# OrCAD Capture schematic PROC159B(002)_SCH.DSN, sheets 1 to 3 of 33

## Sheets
1 11. CURRENT MONITORING DEVICES: size C; title: CURRENT MONITORING DEVICES; rev: B
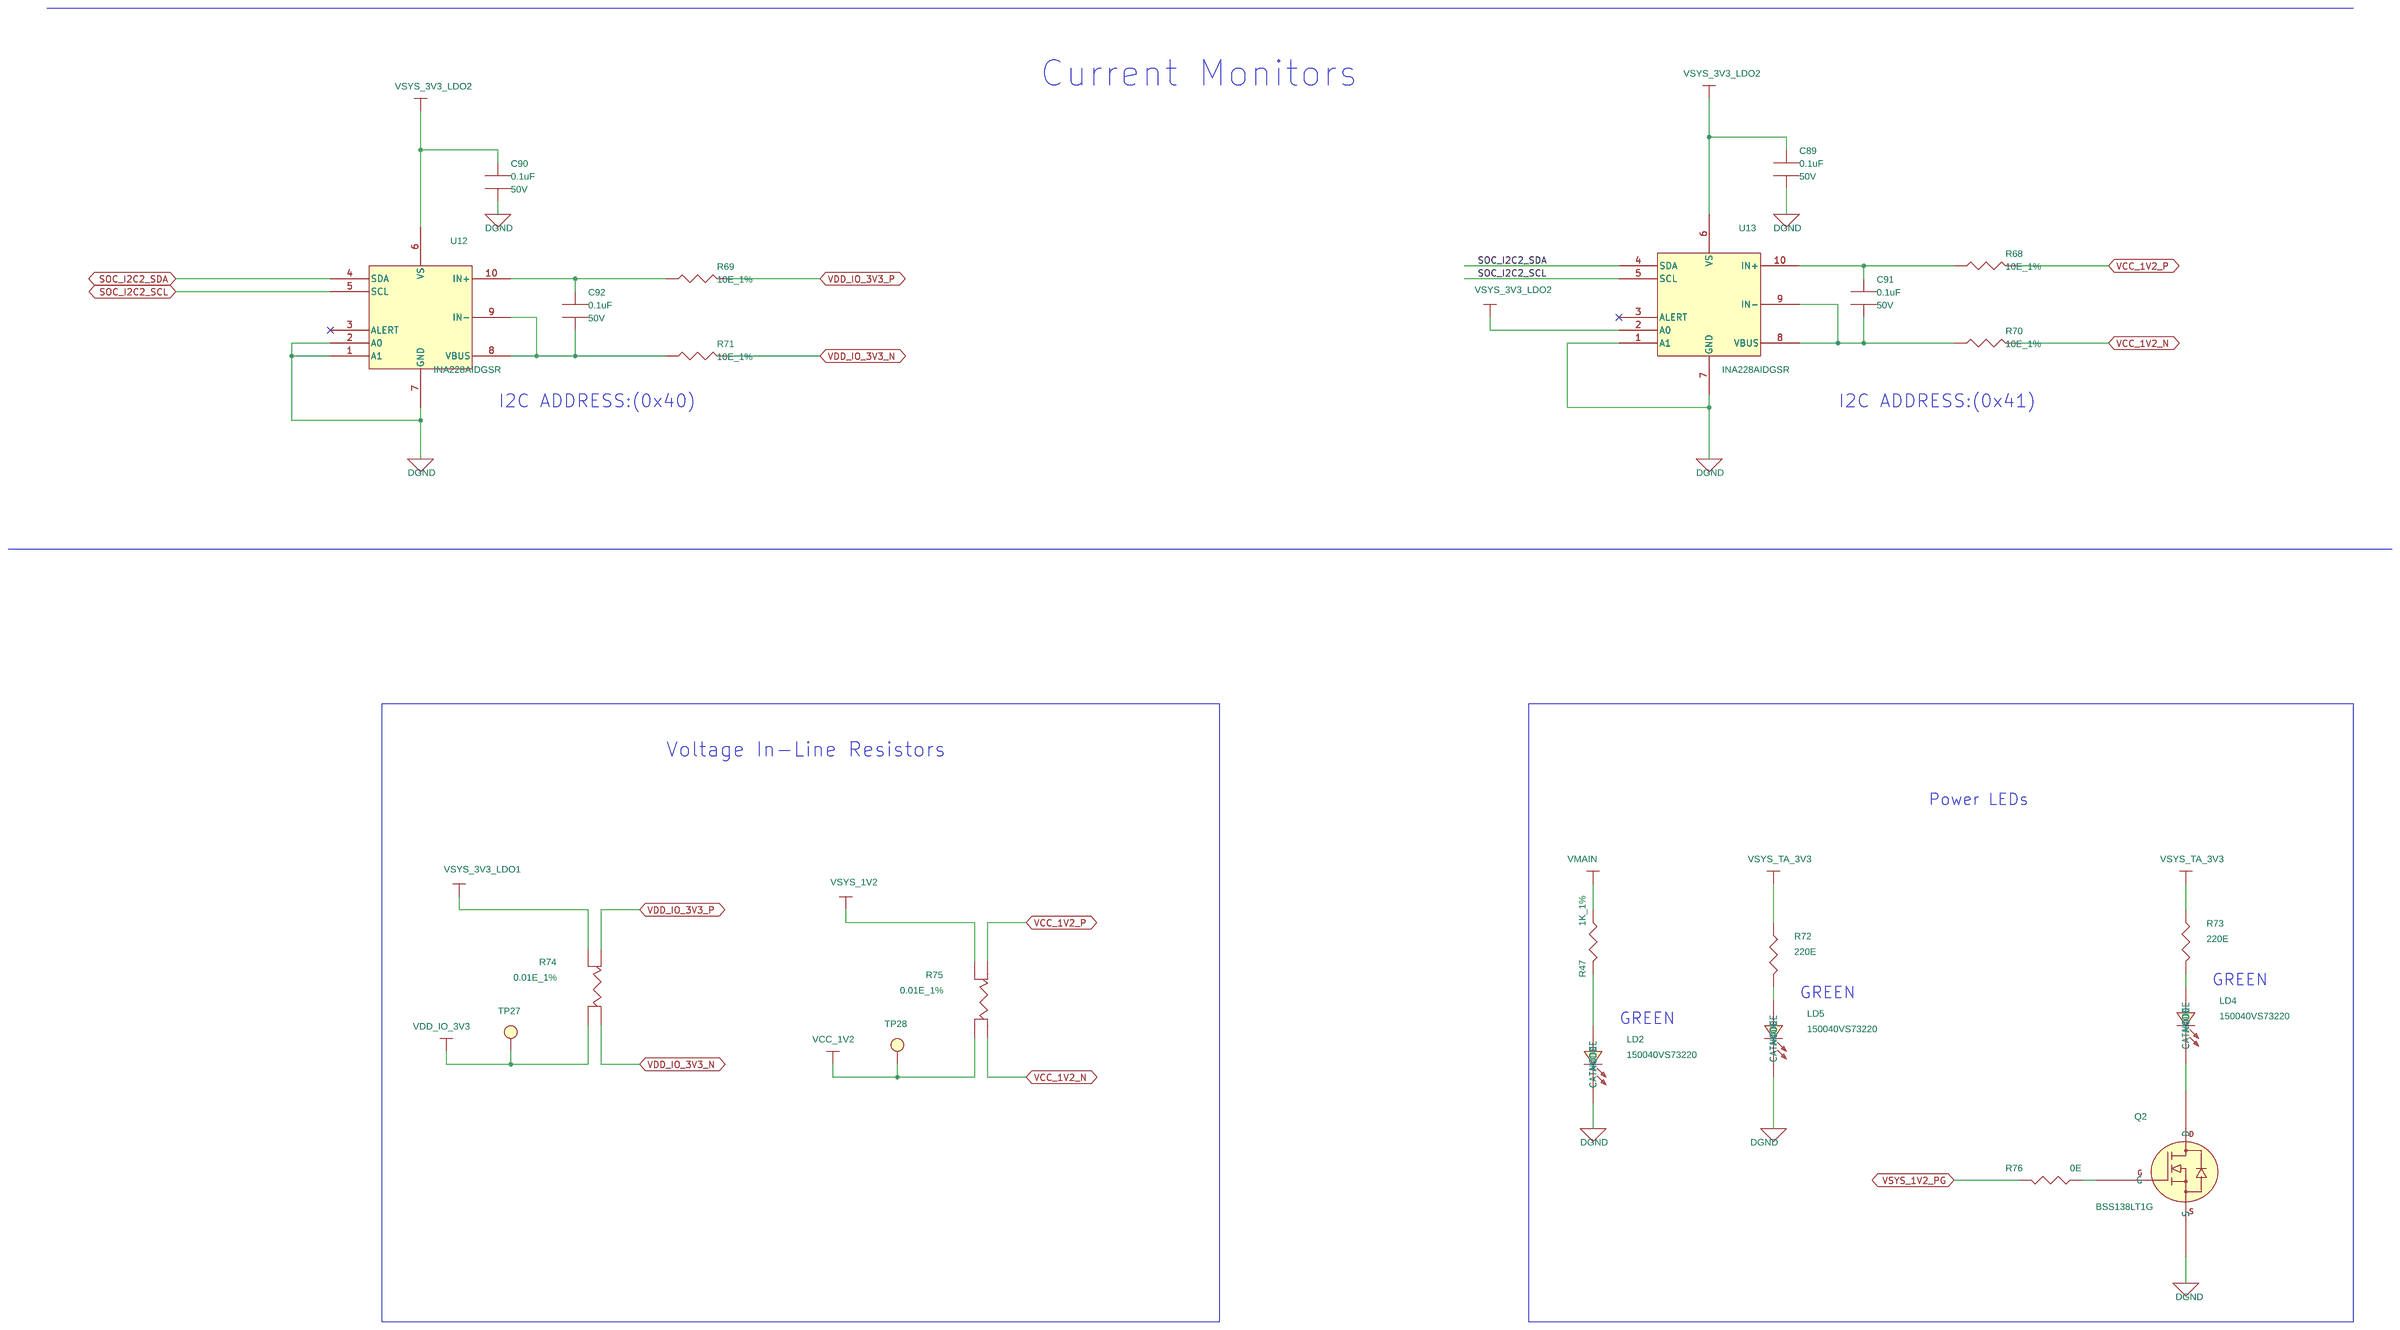
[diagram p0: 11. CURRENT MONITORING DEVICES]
2 30. ADC  MUXES: size C; title: ADC MUXES
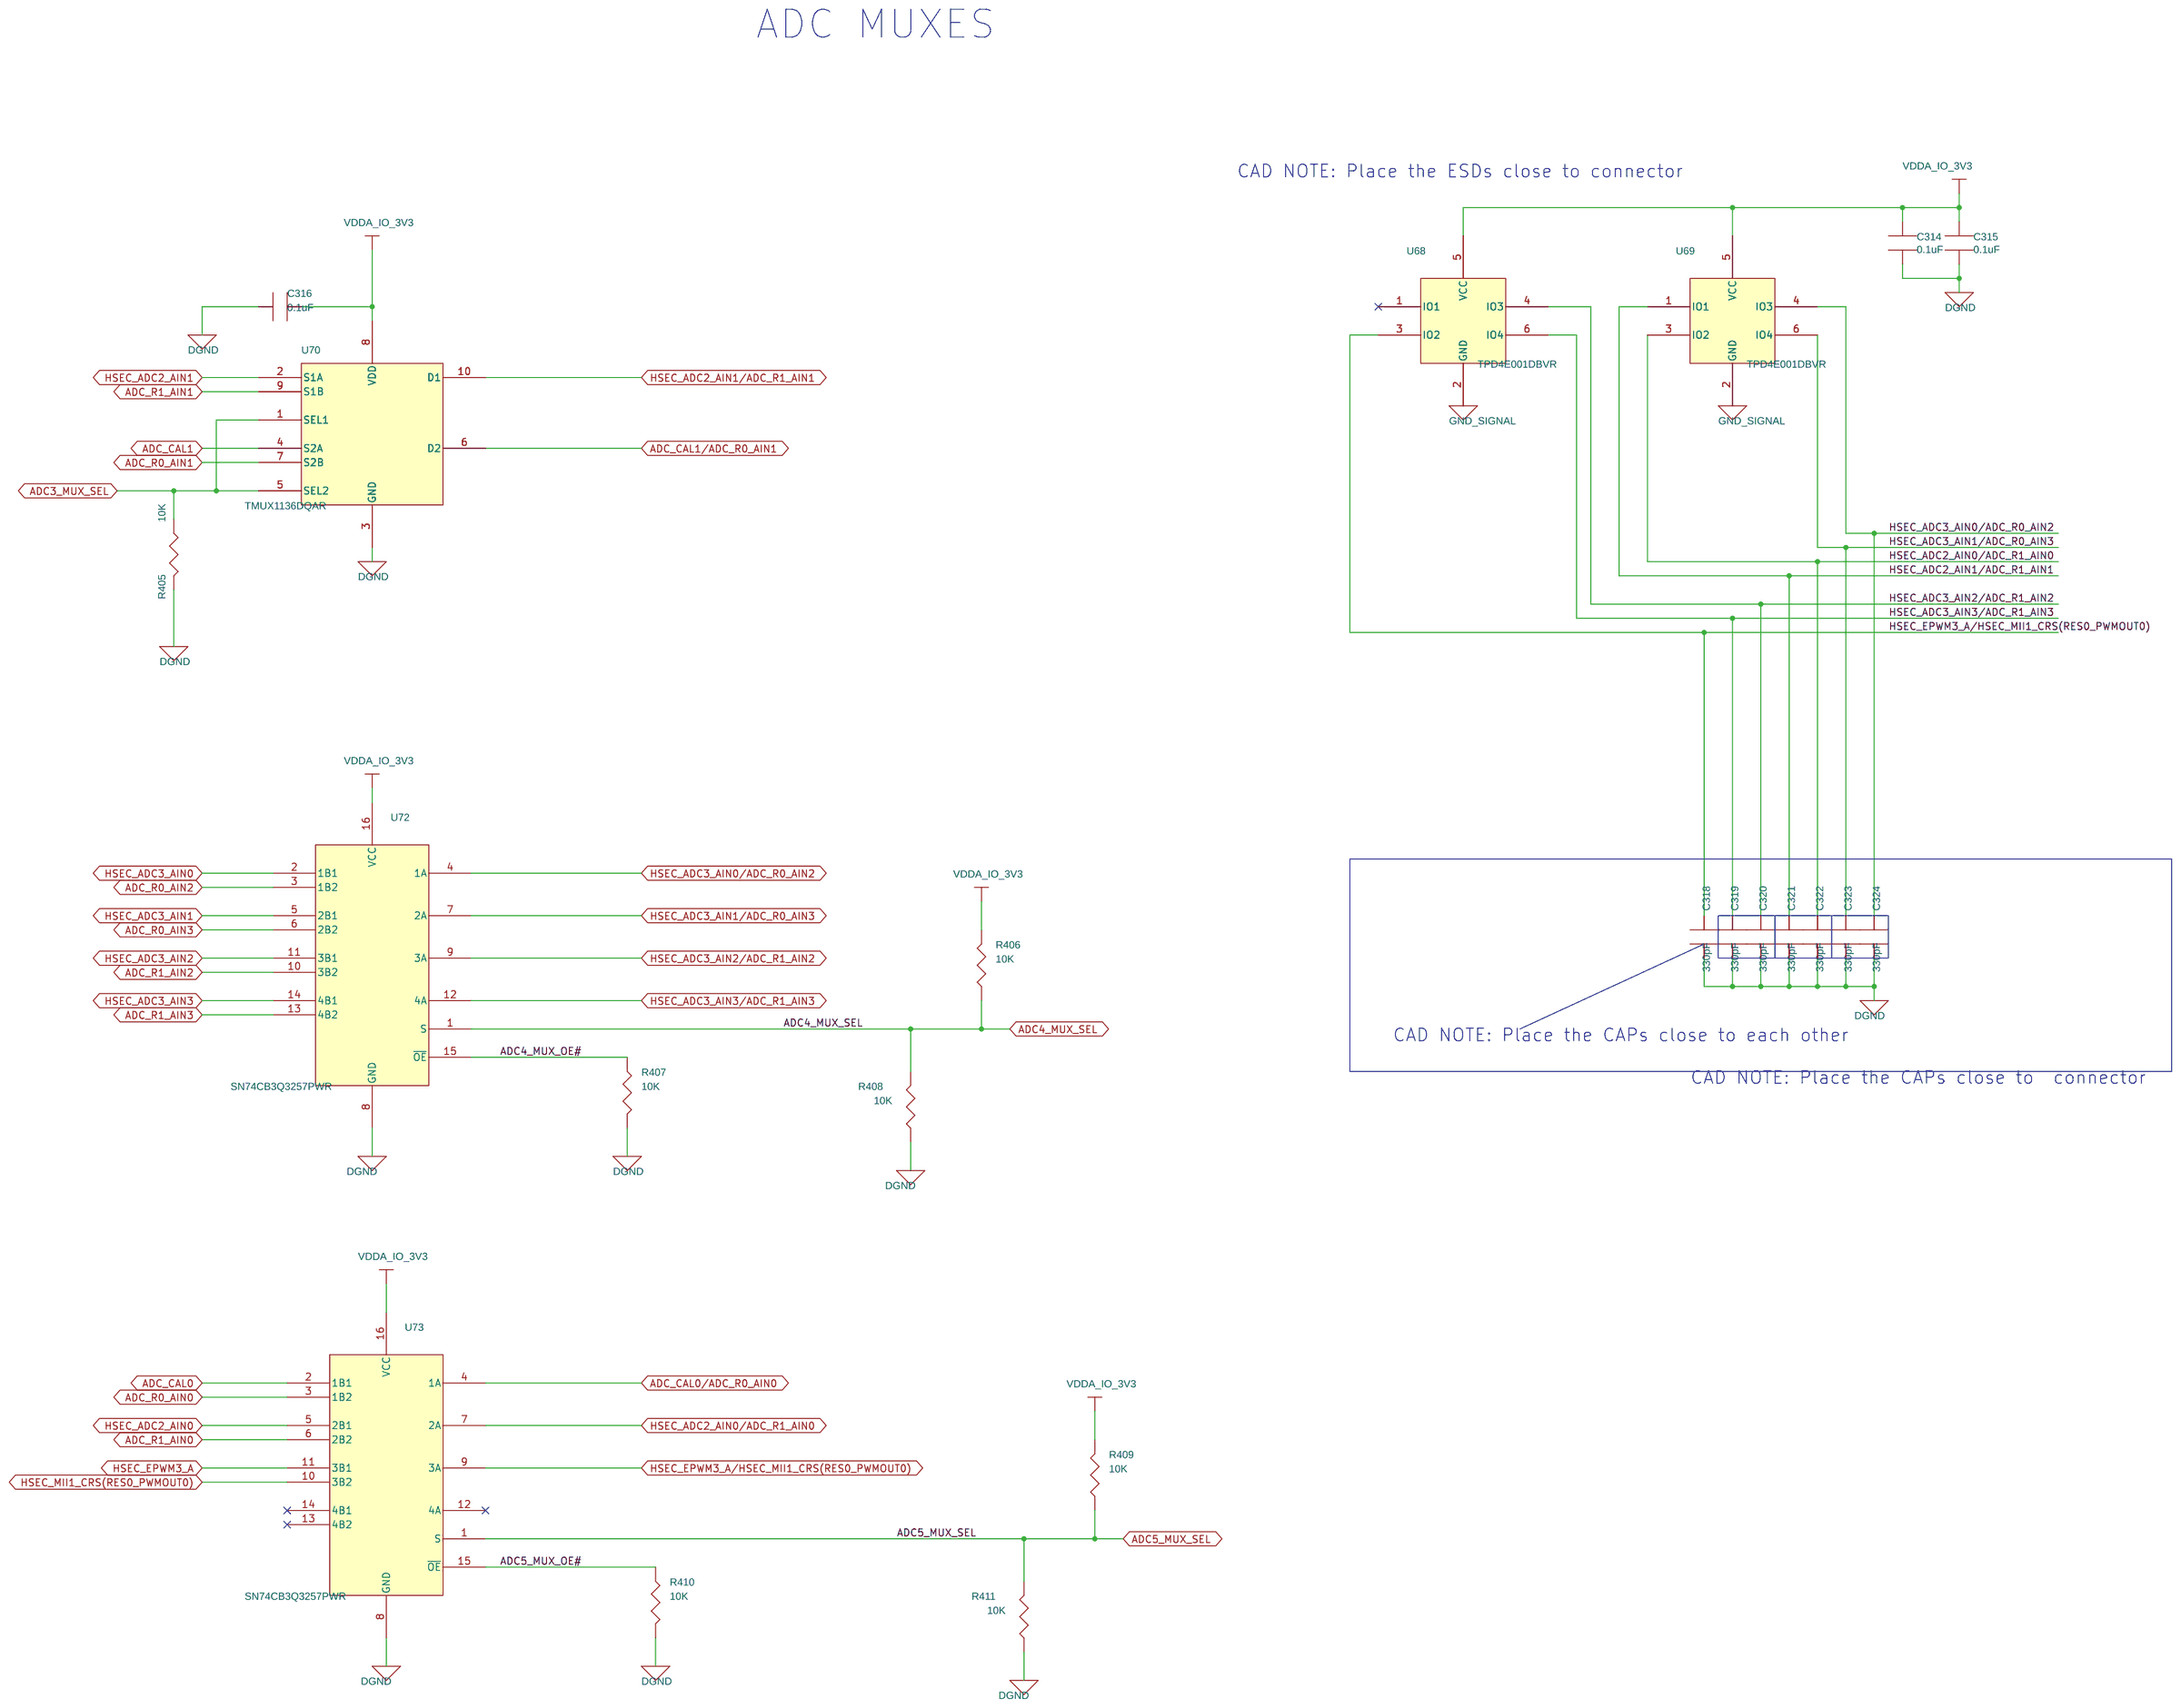
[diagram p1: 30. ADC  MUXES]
3 27. AUTOMATION SIGNALS BUFFER: size C; title: AUTOMATION SIGNALS BUFFER
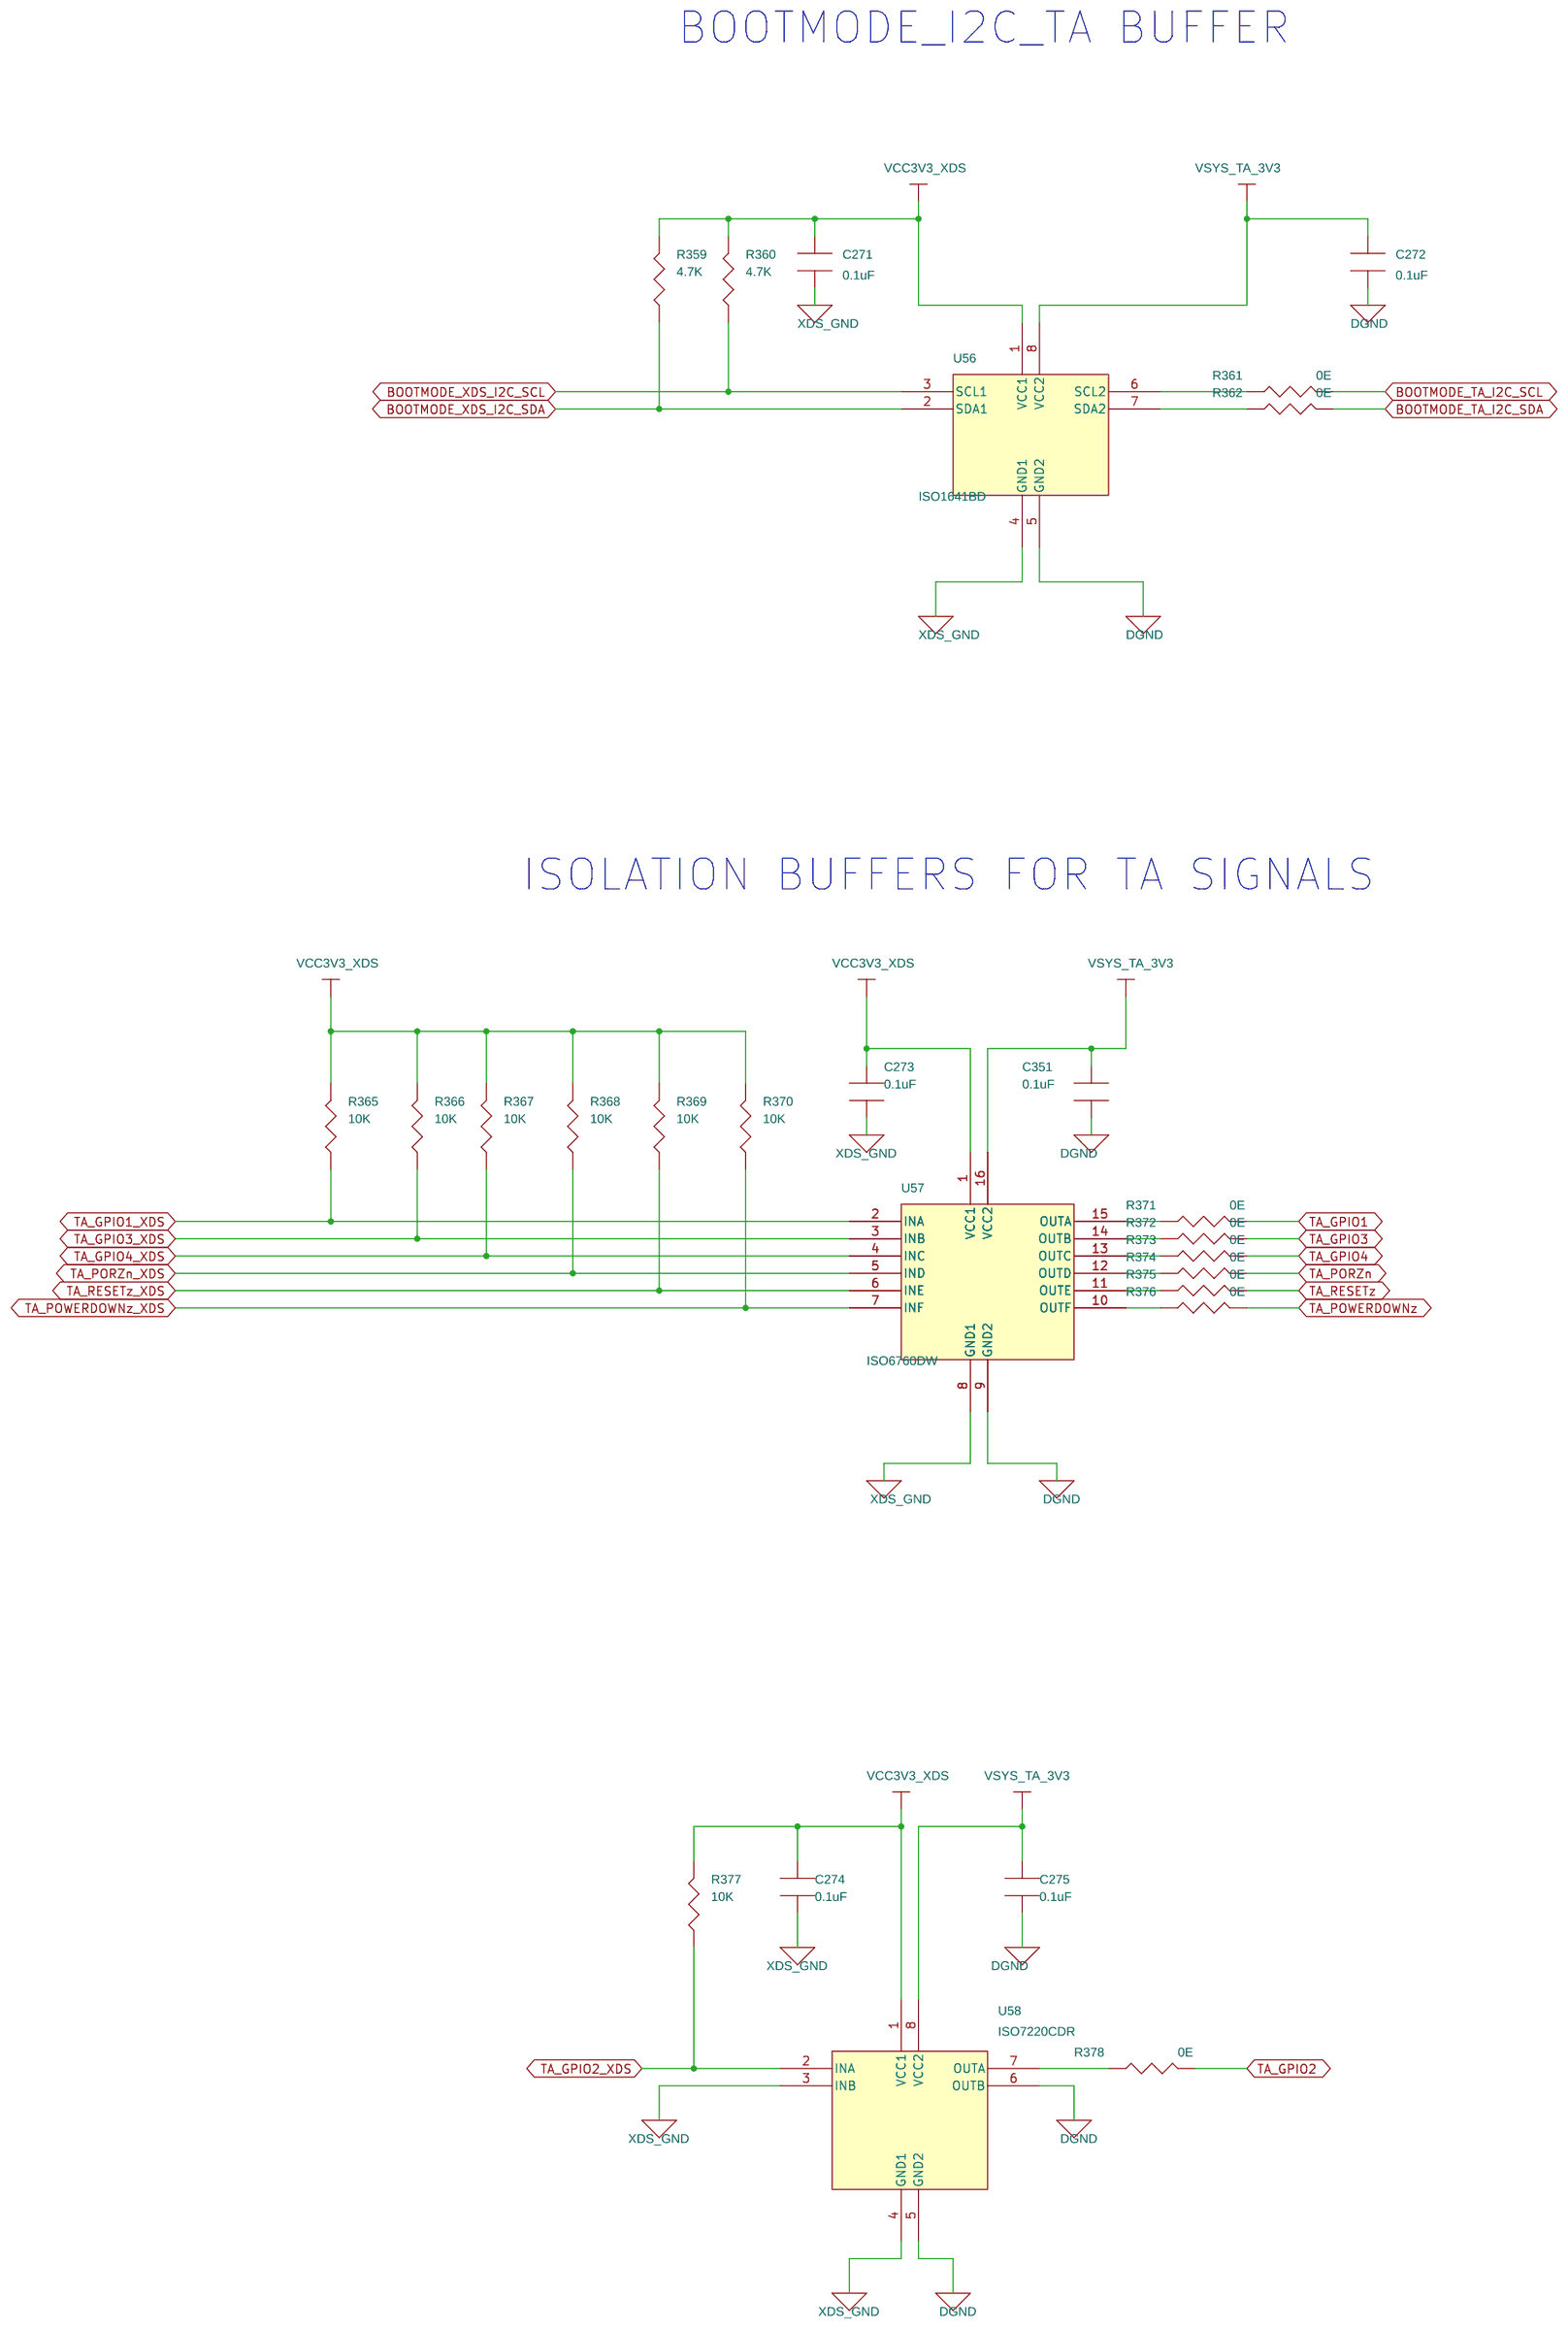
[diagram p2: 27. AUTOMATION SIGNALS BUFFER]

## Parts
sheet 11. CURRENT MONITORING DEVICES
C89  0.1uF  [CAP0402_0-75]
C90  0.1uF  [CAP0402_0-75]
C91  0.1uF  [CAP0402_0-75]
C92  0.1uF  [CAP0402_0-75]
LD2  150040VS73220  [LED_150040GS73220_40X20_SMD_0-4]
LD4  150040VS73220  [LED_150040GS73220_40X20_SMD_0-4]
LD5  150040VS73220  [LED_150040GS73220_40X20_SMD_0-4]
Q2  BSS138LT1G  [SOT23-123_1-2]
R47  1K_1%  [RES0402_0-5]
R68  10E_1%  [RES0402_0-5]
R69  10E_1%  [RES0402_0-5]
R70  10E_1%  [RES0402_0-5]
R71  10E_1%  [RES0402_0-5]
R72  220E  [RES0402_0-5]
R73  220E  [RES0402_0-5]
R74  0.01E_1%  [RES_FC4L16_0306-4_0-7]
R75  0.01E_1%  [RES_FC4L16_0306-4_0-7]
R76  0E  [RES0402_0-5]
TP27  TP40_SMD  [TP40_SMD]
TP28  TP40_SMD  [TP40_SMD]
U12  INA228AIDGSR  [MSOP10_19-68_120X120_1-1]
U13  INA228AIDGSR  [MSOP10_19-68_120X120_1-1]
sheet 27. AUTOMATION SIGNALS BUFFER
C271  0.1uF  [CAP0201_0-5]
C272  0.1uF  [CAP0201_0-5]
C273  0.1uF  [CAP0201_0-5]
C274  0.1uF  [CAP0201_0-5]
C275  0.1uF  [CAP0201_0-5]
C351  0.1uF  [CAP0201_0-5]
R359  4.7K  [RES0201_0-5]
R360  4.7K  [RES0201_0-5]
R361  0E  [RES0201_0-5]
R362  0E  [RES0201_0-5]
R365  10K  [RES0201_0-5]
R366  10K  [RES0201_0-5]
R367  10K  [RES0201_0-5]
R368  10K  [RES0201_0-5]
R369  10K  [RES0201_0-5]
R370  10K  [RES0201_0-5]
R371  0E  [RES0201_0-5]
R372  0E  [RES0201_0-5]
R373  0E  [RES0201_0-5]
R374  0E  [RES0201_0-5]
R375  0E  [RES0201_0-5]
R376  0E  [RES0201_0-5]
R377  10K  [RES0201_0-5]
R378  0E  [RES0201_0-5]
U56  ISO1641BD  [SOIC8_1-8]
U57  ISO6760DW  [SOIC16_W]
U58  ISO7220CDR  [SOIC8]
sheet 30. ADC  MUXES
C314  0.1uF  [CAP0402_0-75]
C315  0.1uF  [CAP0402_0-75]
C316  0.1uF  [CAP0402_0-75]
C318  330pF  [CAP0402_0-75]
C319  330pF  [CAP0402_0-75]
C320  330pF  [CAP0402_0-75]
C321  330pF  [CAP0402_0-75]
C322  330pF  [CAP0402_0-75]
C323  330pF  [CAP0402_0-75]
C324  330pF  [CAP0402_0-75]
R405  10K  [RES0402_0-5]
R406  10K  [RES0402_0-5]
R407  10K  [RES0402_0-5]
R408  10K  [RES0402_0-5]
R409  10K  [RES0402_0-5]
R410  10K  [RES0402_0-5]
R411  10K  [RES0402_0-5]
U68  TPD4E001DBVR  [SOT23-6]
U69  TPD4E001DBVR  [SOT23-6]
U70  TMUX1136DQAR  [USON10_TMUX1204_40X100_0-6]
U72  SN74CB3Q3257PWR  [TSSOP16_25-59_205X180]
U73  SN74CB3Q3257PWR  [TSSOP16_25-59_205X180]

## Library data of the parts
C89-C92 C314-C316 = CAP: CAP CERAMIC 0.1uF 50V 10% X7R 0402; Chkd/date: MANIRAJA/261020; Crtd /date: ALVY/211020; Custom_Duty: 15%; Customs_HS_Code: 85322990; Distributor_name: DIGIKEY; Distributor_part_number: 490-10700-1-ND; Footprint Path: Y:\MIS_DATABASE\Library\ALTIUM_TOOL\PCB_FOOTPRINTS\Altium_Footprint_Lib.PcbLib; Height: 0.55MM; Library Path: Y:\MIS_DATABASE\Library\ALTIUM_TOOL\SCHEMATICS_PARTS\MS_DISCRETE_Library.schlib; Mfr_name: MURATA; Mfr_part_number: GRM155R71H104KE14D; Mistral Part No: 120011100014-R; Package: 0402; Part_type: CAPACITORS\CERAMIC; Project: J7_CP; RoHS: RoHS; Temperature: -55°C+125°C; Tolerance: 10%; Voltage: 50V; Wattage: NA; Weight: 3.1mg; Datasheet: Y:\MIS_DATABASE\DATASHEETS\CAPACITORS\GRM155R71H104KE14.PDF
LD2 LD4 LD5 = DIODE_LED: DIODE LED BRIGHT GREEN SMD; Chkd/date: MANIRAJA/261120; Crtd /date: ALVY/261120; Custom_Duty: 24%; Customs_HS_Code: 85439000; Distributor_name: DIGIKEY; Distributor_part_number: 732-13425-1-ND; Footprint Path: Y:\MIS_DATABASE\Library\ALTIUM_TOOL\PCB_FOOTPRINTS\Altium_Footprint_Lib.PcbLib; Height: 0.35MM; Library Path: Y:\MIS_DATABASE\Library\ALTIUM_TOOL\SCHEMATICS_PARTS\MS_OPTO_Library.schlib; Mfr_name: WURTH ELECTRONIK; Mistral Part No: 130020110071-R; Package: SMD; Part_type: OPTO\LED; Project: AM64X_SKEVM; RoHS: RoHS; Temperature: -40°C+85°C; Tolerance: NA; Voltage: NA; Wattage: NA; Weight: 29.3mg; Datasheet: Y:\MIS_DATABASE\DATASHEETS\DISCRETES\LEDS\150040VS73220.PDF
Q2 = MOSFET_BSS138W: IC MOSFET N-CHANNEL 50V 200mA SOT23-3; Chkd/date: MANIRAJA/250219; Crtd /date: JEBRAN/060416; Custom_Duty: 15%; Customs_HS_Code: 85423100; Distributor_name: DIGIKEY; Distributor_part_number: BSS138LT1GOSCT-ND; Footprint Path: Y:\MIS_DATABASE\Library\ALTIUM_TOOL\PCB_FOOTPRINTS\Altium_Footprint_Lib.PcbLib; Height: 1.11MM; Library Path: Y:\MIS_DATABASE\Library\ALTIUM_TOOL\SCHEMATICS_PARTS\MS_MOSFET_Library.schlib; Mfr_name: ON SEMICONDUCTOR; Mistral Part No: 142016040001-R; Package: SOT23-3; Part_type: ICS\POWER\MOSFET; Project: LRDE_ABCM; RoHS: RoHS; Temperature: -55°C+150°C; Tolerance: NA; Voltage: NA; Wattage: NA; Weight: 8mg; Datasheet: Y:\MIS_DATABASE\DATASHEETS\DISCRETES\TRANSISTORS_FETS\BSS138LT1G.PDF
R47 = RESISTOR: RES 1K 1/10W 1% 0402; Chkd/date: VASANTHA/281216; Crtd /date: MAZHAR/150506; Custom_Duty: 15%; Customs_HS_Code: 85332119; Distributor_name: DIGIKEY; Distributor_part_number: P1.00KLCT-ND; Footprint Path: Y:\MIS_DATABASE\Library\ALTIUM_TOOL\PCB_FOOTPRINTS\Altium_Footprint_Lib.PcbLib; Height: 0.40MM; Library Path: Y:\MIS_DATABASE\Library\ALTIUM_TOOL\SCHEMATICS_PARTS\MS_DISCRETE_Library.schlib; Mfr_name: PANASONIC-ECG; Mfr_part_number: ERJ-2RKF1001X; Mistral Part No: 110009030411-R; Package: 0402; Part_type: RESISTORS\FIXED; Project: VOCERA; RoHS: RoHS; Temperature: -55°C+155°C; Tolerance: 1%; Voltage: NA; Wattage: 1/10W; Weight: 0.8mg; Datasheet: Y:\MIS_DATABASE\DATASHEETS\RESISTORS\PAN-ERJSER_NOV17.PDF
R68-R71 = RESISTOR: RES 10E 1/16W 1% 0402; Chkd/date: MANIRAJA/070218; Crtd /date: ALVY/070218; Custom_Duty: 15%; Customs_HS_Code: 85332119; Distributor_name: DIGIKEY; Distributor_part_number: 311-10.0LRCT-ND; Footprint Path: Y:\MIS_DATABASE\Library\ALTIUM_TOOL\PCB_FOOTPRINTS\Altium_Footprint_Lib.PcbLib; Height: 0.40MM; Library Path: Y:\MIS_DATABASE\Library\ALTIUM_TOOL\SCHEMATICS_PARTS\MS_DISCRETE_Library.schlib; Mfr_name: YAGEO AMERICA; Mfr_part_number: RC0402FR-0710RL; Mistral Part No: 110018020004-R; Package: 0402; Part_type: RESISTORS\FIXED; Project: TI_MAXIE_CPB; RoHS: RoHS; Temperature: -55°C+155°C; Tolerance: 1%; Voltage: NA; Wattage: 1/16W; Weight: 0.65mg; Datasheet: Y:\MIS_DATABASE\DATASHEETS\RESISTORS\RCXXXXL-SER_MAR18.PDF
R72 R73 = RESISTOR: RES 220E 1/10W 5% 0402; Chkd/date: VASANTHA/291216; Crtd /date: GEETHA/260406; Custom_Duty: 15%; Customs_HS_Code: 85332119; Distributor_name: DIGIKEY; Distributor_part_number: P220JCT-ND; Footprint Path: Y:\MIS_DATABASE\Library\ALTIUM_TOOL\PCB_FOOTPRINTS\Altium_Footprint_Lib.PcbLib; Height: 0.40MM; Library Path: Y:\MIS_DATABASE\Library\ALTIUM_TOOL\SCHEMATICS_PARTS\MS_DISCRETE_Library.schlib; Mfr_name: PANASONIC-ECG; Mfr_part_number: ERJ-2GEJ221X; Mistral Part No: 110009030506-R; Package: 0402; Part_type: RESISTORS\FIXED; Project: RED EYE; RoHS: RoHS; Temperature: -55°C+155°C; Tolerance: 5%; Voltage: NA; Wattage: 1/10W; Weight: 0.8mg; Datasheet: Y:\MIS_DATABASE\DATASHEETS\RESISTORS\PAN-ERJSER_NOV17.PDF
R74 R75 = RESISTOR-4TERM: RES CURRENT SENSE 0.01E 1/4W 1% 0306-4; Chkd/date: MANIRAJA/261018; Crtd /date: ALVY/261018; Custom_Duty: 15%; Customs_HS_Code: 85332119; Distributor_name: DIGIKEY; Distributor_part_number: FC4L16R010FERCT-ND; Footprint Path: Y:\MIS_DATABASE\Library\ALTIUM_TOOL\PCB_FOOTPRINTS\Altium_Footprint_Lib.PcbLib; Height: 0.70MM; Library Path: Y:\MIS_DATABASE\Library\ALTIUM_TOOL\SCHEMATICS_PARTS\MS_DISCRETE_Library.schlib; Mfr_name: OHMITE; Mfr_part_number: FC4L16R010FER; Mistral Part No: 110018100017-R; Package: 0306-4; Part_type: RESISTORS\FIXED; Project: TI_J7ES_EVM_SOM; RoHS: RoHS; Temperature: -40°C+125°C; Tolerance: 1%; Voltage: NA; Wattage: 1/4W; Weight: 4mg; Datasheet: Y:\MIS_DATABASE\DATASHEETS\RESISTORS\FC4L-SERIES.PDF
R76 = RESISTOR: RES 0E 1/10W JUMPER 0402; Chkd/date: VASANTHA/061216; Crtd /date: NAVEED/201014; Custom_Duty: 15%; Customs_HS_Code: 85332119; Distributor_name: DIGIKEY; Distributor_part_number: P0.0JCT-ND; Footprint Path: Y:\MIS_DATABASE\Library\ALTIUM_TOOL\PCB_FOOTPRINTS\Altium_Footprint_Lib.PcbLib; Height: 0.40MM; IBISSP_MODLES: VALUE REPEATING 2 TIME; Library Path: Y:\MIS_DATABASE\Library\ALTIUM_TOOL\SCHEMATICS_PARTS\MS_DISCRETE_Library.schlib; Mfr_name: PANASONIC-ECG; Mfr_part_number: ERJ-2GE0R00X; Mistral Part No: 110018030052-R; Package: 0402; Part_type: RESISTORS\FIXED; Project: AEGIS POM; RoHS: RoHS; Temperature: -55°C+155°C; Tolerance: NA; Voltage: NA; Wattage: 1/10W; Weight: 0.8mg; Datasheet: Y:\MIS_DATABASE\DATASHEETS\RESISTORS\PAN-ERJSER_NOV17.PDF
TP27 TP28 = TESTPOINT: TESTPOINT CIR 40 SMD; Chkd/date: MAZHAR/190505; Crtd /date: MAZHAR/190505; Distributor_name: NA; Distributor_part_number: NA; Footprint Path: Y:\MIS_DATABASE\Library\ALTIUM_TOOL\PCB_FOOTPRINTS\Altium_Footprint_Lib.PcbLib; Height: NA; Library Path: Y:\MIS_DATABASE\Library\ALTIUM_TOOL\SCHEMATICS_PARTS\MS_DISCRETE_Library.schlib; MECHANICAL 3D STEP FILE: NA; Mfr_name: LOCAL; Mistral Part No: 130009030933; Package: SMD; Project: RAINIER-3; RoHS: NA; Temperature: NA; Tolerance: NA; Voltage: NA; Wattage: NA; Weight: NA; Datasheet: NA
U12 U13 = INA226AIDGS_MSOP10: IC 85V 20BIT POWER/ENERGY/CHARGE MONITOR WITH I2C INTERFACE VSSOP10; Chkd/date: MANIRAJA/041021; Crtd /date: ALVY/011021; Custom_Duty: 15%; Customs_HS_Code: 85423100; Distributor_name: DIGIKEY; Distributor_part_number: 296-INA228AIDGSRCT-ND; Footprint Path: Y:\MIS_DATABASE\Library\ALTIUM_TOOL\PCB_FOOTPRINTS\Altium_Footprint_Lib.PcbLib; Height: 1.10MM; Library Path: Y:\MIS_DATABASE\Library\ALTIUM_TOOL\SCHEMATICS_PARTS\MS_MISCPOWER_Library.schlib; Mfr_name: TEXAS INSTRUMENTS; Mistral Part No: 142021100003-R; Package: VSSOP10; Part_type: ICS\POWER\MANAGEMENT; Project: ENEKOM_SMART SENSOR SYSTEM; RoHS: RoHS; Temperature: -40°C+125°C; Tolerance: NA; Voltage: NA; Wattage: NA; Weight: NA; Datasheet: Y:\MIS_DATABASE\DATASHEETS\ICS\POWER\INA228A.PDF
C271-C275 C351 = CAP: CAP CERAMIC 0.1uF 16V 10% X5R 0201; Alt_Mfr_name: YAGEO AMERICA; Alt_Mfr_part_number: CC0402KRX5R8BB104; Chkd/date: MANIRAJA/230118; Crtd /date: MANIRAJA/230118; Custom_Duty: 15%; Customs_HS_Code: 85322990; Distributor_name: DIGIKEY; Distributor_part_number: 490-14305-1-ND; Footprint Path: Y:\MIS_DATABASE\Library\ALTIUM_TOOL\PCB_FOOTPRINTS\Altium_Footprint_Lib.PcbLib; Height: 0.33MM; Library Path: Y:\MIS_DATABASE\Library\ALTIUM_TOOL\SCHEMATICS_PARTS\MS_DISCRETE_Library.schlib; Mfr_name: MURATA; Mfr_part_number: GRM033R61C104KE14D; Mistral Part No: 120009030072-R; Package: 0201; Part_type: CAPACITORS\CERAMIC; Project: TI_MAXIE_CPB; RoHS: RoHS; Temperature: -55°C+85°C; Tolerance: 10%; Voltage: 16V; Wattage: NA; Weight: 0.33mg; Datasheet: Y:\MIS_DATABASE\DATASHEETS\CAPACITORS\GRM033R61C104KE14.PDF
R359 R360 = RESISTOR: RES 4.7K 1/20W 5% 0201; Chkd/date: MANIRAJA/200921; Crtd /date: ALVY/200921; Custom_Duty: 15%; Customs_HS_Code: 85332119; Distributor_name: DIGIKEY; Distributor_part_number: 311-4.7KNCT-ND; Footprint Path: Y:\MIS_DATABASE\Library\ALTIUM_TOOL\PCB_FOOTPRINTS\Altium_Footprint_Lib.PcbLib; Height: 0.26MM; Library Path: Y:\MIS_DATABASE\Library\ALTIUM_TOOL\SCHEMATICS_PARTS\MS_DISCRETE_Library.schlib; Mfr_name: YAGEO AMERICA; Mfr_part_number: RC0201JR-074K7L; Mistral Part No: 110021090007-R; Package: 0201; Part_type: RESISTORS\FIXED; Project: TI_AM62x SKEVM_BRD; RoHS: RoHS; Temperature: -55°C+125°C; Tolerance: 5%; Voltage: NA; Wattage: 1/20W; Weight: 0.17mg; Datasheet: Y:\MIS_DATABASE\DATASHEETS\RESISTORS\RCXXXXL-SER_MAR18.PDF
R361 R362 R371-R376 R378 = RESISTOR: RES 0E 1/20W 5% 0201; Chkd/date: NAVEED/301214; Crtd /date: MUDDU/120710; Custom_Duty: 15%; Customs_HS_Code: 85332119; Distributor_name: DIGIKEY; Distributor_part_number: 311-0.0NCT-ND; Footprint Path: Y:\MIS_DATABASE\Library\ALTIUM_TOOL\PCB_FOOTPRINTS\Altium_Footprint_Lib.PcbLib; Height: 0.26MM; Library Path: Y:\MIS_DATABASE\Library\ALTIUM_TOOL\SCHEMATICS_PARTS\MS_DISCRETE_Library.schlib; Mfr_name: YAGEO AMERICA; Mfr_part_number: RC0201JR-070RL; Mistral Part No: 110010070067-R; Package: 0201; Part_type: RESISTORS\FIXED; Project: PB_BUGBASE; RoHS: RoHS; Temperature: -55°C+125°C; Tolerance: 5%; Voltage: NA; Wattage: 1/20W; Weight: 0.17mg; Datasheet: Y:\MIS_DATABASE\DATASHEETS\RESISTORS\RCXXXXL-SER_MAR18.PDF
R365-R370 R377 = RESISTOR: RES 10K 1/20W 5% 0201; Chkd/date: MANIRAJA/050517; Crtd /date: MANIRAJA/050517; Custom_Duty: 15%; Customs_HS_Code: 85332119; Distributor_name: DIGIKEY; Distributor_part_number: 311-10KNCT-ND; Footprint Path: Y:\MIS_DATABASE\Library\ALTIUM_TOOL\PCB_FOOTPRINTS\Altium_Footprint_Lib.PcbLib; Height: 0.26MM; Library Path: Y:\MIS_DATABASE\Library\ALTIUM_TOOL\SCHEMATICS_PARTS\MS_DISCRETE_Library.schlib; Mfr_name: YAGEO AMERICA; Mfr_part_number: RC0201JR-0710KL; Mistral Part No: 110010070051-R; Package: 0201; Part_type: RESISTORS\FIXED; Project: GOLDEN-I LITE; RoHS: RoHS; Temperature: -55°C+125°C; Tolerance: 5%; Voltage: NA; Wattage: 1/20W; Weight: 0.17mg; Datasheet: Y:\MIS_DATABASE\DATASHEETS\RESISTORS\RCXXXXL-SER_MAR18.PDF
U56 = ISO1641B_SOIC8: IC HOT-SWAPPABLE BIDIRECTIONAL I2C ISOLATORS WITH ENHANCED EMC AND GPIOS SOIC8; Chkd/date: PRAVEEN/180423; Crtd /date: PRAVEEN/180423; Custom_Duty: 15%; Customs_HS_Code: 85423100; Distributor_name: DIGIKEY; Distributor_part_number: 296-ISO1641BDRCT-ND; Footprint Path: Y:\MIS_DATABASE\Library\ALTIUM_TOOL\PCB_FOOTPRINTS\Altium_Footprint_Lib.PcbLib; Height: 1.75MM; Library Path: Y:\MIS_DATABASE\Library\ALTIUM_TOOL\SCHEMATICS_PARTS\MS_MISC_Library.schlib; Mfr_name: TEXAS INSTRUMENTS; Mfr_part_number: ISO1641BDR; Mistral Part No: 141023040007-R; Package: SOIC8; Part_type: ICS\DIGITAL\ISOLATOR; Project: AM263P_CC; RoHS: RoHS; Temperature: -40°C+125°C; Tolerance: NA; Voltage: NA; Wattage: NA; Weight: 540mg; Datasheet: Y:\MIS_DATABASE\DATASHEETS\ICS\MISC\ISO1641BD.PDF
U57 = ISO6760_SOIC16: IC SIX-CHANNEL REINFORCED DIGITAL ISOLATORS WITH ROBUST EMC SOIC16; Chkd/date: PRAVEEN/180423; Crtd /date: PRAVEEN/180423; Custom_Duty: 15%; Customs_HS_Code: 85423100; Distributor_name: DIGIKEY; Distributor_part_number: 296-ISO6760DWRCT-ND; Height: 2.65MM; Mfr_name: TEXAS INSTRUMENTS; Mfr_part_number: ISO6760DWR; Mistral Part No: 141023040008-R; Package: SOIC16; Part_type: ICS\DIGITAL\ISOLATOR; Project: AM263P_CC; RoHS: RoHS; Temperature: -40°C+125°C; Tolerance: NA; Voltage: NA; Wattage: NA; Weight: NA; Datasheet: Y:\MIS_DATABASE\DATASHEETS\ICS\INTERFACE\ISO676XDW.PDF
U58 = ISO7220XD_SOIC8: IC DUAL-CHANNEL 25MBpS DIGITAL ISOLATORS SOIC8; Chkd/date: NAVEED/100715; Crtd /date: VASANTHA/060814; Custom_Duty: 15%; Customs_HS_Code: 85423100; Distributor_name: DIGIKEY; Distributor_part_number: 296-21953-1-ND; Height: 1.75MM; Mfr_name: TEXAS INSTRUMENTS; Mistral Part No: 141014080006-R; Part_type: ICS\MISC; Project: ZK_BIOMETRIC; RoHS: RoHS; Temperature: -40°C+125°C; Tolerance: NA; Voltage: NA; Wattage: NA; Weight: NA; Datasheet: Y:\MIS_DATABASE\DATASHEETS\ICS\POWER\ISO722X.PDF
C318-C324 = CAP: CAP CERAMIC 330pF 50V 5% C0G(NP0) 0402; Chkd/date: MANIRAJA/130617; Crtd /date: MAZHAR/221206; Custom_Duty: 15%; Customs_HS_Code: 85322990; Distributor_name: DIGIKEY; Distributor_part_number: 490-1295-1-ND; Footprint Path: Y:\MIS_DATABASE\Library\ALTIUM_TOOL\PCB_FOOTPRINTS\Altium_Footprint_Lib.PcbLib; Height: 0.55MM; Library Path: Y:\MIS_DATABASE\Library\ALTIUM_TOOL\SCHEMATICS_PARTS\MS_DISCRETE_Library.schlib; Mfr_name: MURATA; Mfr_part_number: GRM1555C1H331JA01D; Mistral Part No: 120009030375-R; Package: 0402; Part_type: CAPACITORS\CERAMIC; Project: ADR1B; RoHS: RoHS; Temperature: -55°C+125°C; Tolerance: 5%; Voltage: 50V; Wattage: NA; Weight: 6mg; Datasheet: Y:\MIS_DATABASE\DATASHEETS\CAPACITORS\MURATA-GXX-SER_NOV17.PDF
R405 R406 R409 = RESISTOR: RES 10K 1/16W 5% 0402; Chkd/date: VASANTHA/061216; Crtd /date: MAZHAR/230805; Custom_Duty: 15%; Customs_HS_Code: 85332119; Distributor_name: DIGIKEY; Distributor_part_number: 311-10KJRCT-ND; Footprint Path: Y:\MIS_DATABASE\Library\ALTIUM_TOOL\PCB_FOOTPRINTS\Altium_Footprint_Lib.PcbLib; Height: 0.40MM; Library Path: Y:\MIS_DATABASE\Library\ALTIUM_TOOL\SCHEMATICS_PARTS\MS_DISCRETE_Library.schlib; Mfr_name: YAGEO AMERICA; Mfr_part_number: RC0402JR-0710KL; Mistral Part No: 110011060021-R; Package: 0402; Part_type: RESISTORS\FIXED; Project: HSE; RoHS: RoHS; Temperature: -55°C+155°C; Tolerance: 5%; Voltage: NA; Wattage: 1/16W; Weight: 0.65mg; Datasheet: Y:\MIS_DATABASE\DATASHEETS\RESISTORS\RCXXXXL-SER_MAR18.PDF
R407 R408 R410 R411 = RESISTOR: RES 10K 1/16W 5% 0402; Assembly_Instruction: DNI; Chkd/date: VASANTHA/061216; Crtd /date: MAZHAR/230805; Custom_Duty: 15%; Customs_HS_Code: 85332119; Distributor_name: DIGIKEY; Distributor_part_number: 311-10KJRCT-ND; Footprint Path: Y:\MIS_DATABASE\Library\ALTIUM_TOOL\PCB_FOOTPRINTS\Altium_Footprint_Lib.PcbLib; Height: 0.40MM; Library Path: Y:\MIS_DATABASE\Library\ALTIUM_TOOL\SCHEMATICS_PARTS\MS_DISCRETE_Library.schlib; Mfr_name: YAGEO AMERICA; Mfr_part_number: RC0402JR-0710KL; Mistral Part No: 110011060021-R; Package: 0402; Part_type: RESISTORS\FIXED; Project: HSE; RoHS: RoHS; Temperature: -55°C+155°C; Tolerance: 5%; Voltage: NA; Wattage: 1/16W; Weight: 0.65mg; Datasheet: Y:\MIS_DATABASE\DATASHEETS\RESISTORS\RCXXXXL-SER_MAR18.PDF
U68 U69 = TPD4E001_SOT23-6: IC 4CH ESD-PROTECTION ARRAY SOT23-6; Chkd/date: USMAN/250112; Crtd /date: CHAITHANYA/190112; Custom_Duty: 15%; Customs_HS_Code: 85423100; Distributor_name: DIGIKEY; Distributor_part_number: 296-28203-1-ND; Height: 1.60MM; Mfr_name: TEXAS INSTRUMENTS; Mistral Part No: 141012010005-R; Part_type: ICS\INTERFACE; Project: DM385EVM_BASE-BOARD; RoHS: RoHS; Temperature: NA; Tolerance: NA; Voltage: NA; Wattage: NA; Weight: NA; Datasheet: Y:\MIS_DATABASE\DATASHEETS\ICS\INTERFACE\TPD4E001-SER.PDF
U70 = TMUX1136_USON10: IC 5V LOW-LEAKAGE-CURRENT 2:1 2-CHANNEL PRECISION ANALOG SWITCH USON10; Chkd/date: MANIRAJA/291121; Crtd /date: ALVY/291121; Custom_Duty: 15%; Customs_HS_Code: 85423100; Distributor_name: DIGIKEY; Distributor_part_number: 296-TMUX1136DQARCT-ND; Footprint Path: Y:\MIS_DATABASE\Library\ALTIUM_TOOL\PCB_FOOTPRINTS\Altium_Footprint_Lib.PcbLib; Height: 0.55MM; Library Path: Y:\MIS_DATABASE\Library\ALTIUM_TOOL\SCHEMATICS_PARTS\MS_ANALOG-APPLICATION_Library.schlib; Mfr_name: TEXAS INSTRUMENTS; Mistral Part No: 140121110003-R; Package: USON10; Part_type: ICS\ANALOG\SWITCH; Project: TI_AM263x_CC_BRD; RoHS: RoHS; Temperature: -40°C+125°C; Tolerance: NA; Voltage: NA; Wattage: NA; Weight: 4.3mg; Datasheet: Y:\MIS_DATABASE\DATASHEETS\ICS\ANALOG\TMUX1136.PDF
U72 U73 = SN74CB3Q3257PWR_TSSOP16: IC 4BIT 1-OF-2 FET MULTIPLEXER/DEMULTIPLEXER TSSOP16; Chkd/date: SUHAS/251010; Crtd /date: USMAN/060109; Custom_Duty: 15%; Customs_HS_Code: 85423100; Distributor_name: DIGIKEY; Distributor_part_number: 296-19138-1-ND; Height: 1.20MM; Mfr_name: TEXAS INSTRUMENTS; Mistral Part No: 141009030117-R; Package: TSSOP16; Part_type: ICS\DIGITAL\COMBINATIONAL; Project: OMAP_EVM; RoHS: Sb/ Br FREE; Temperature: -40°C+85°C; Datasheet: Y:\MIS_DATABASE\DATASHEETS\ICS\DIGITAL\COMBINATIONAL\SN74CB3Q3257.PDF

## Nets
DGND: C89.2 C90.2 C272.1 C275.2 C314.2 C315.2 C316.1 C318.2 C319.2 C320.2 C321.2 C322.2 C323.2 C324.2 C351.1 LD2.1(CATHODE) LD5.1(CATHODE) Q2.2(S) R405.2 R407.2 R408.2 R410.2 R411.2 U12.1(A1) U12.2(A0) U12.7(GND) U13.1(A1) U13.7(GND) U56.5(GND2) U57.9(GND2) U58.5(GND2) U58.6(OUTB) U68.2(GND) U69.2(GND) U70.3(GND) U72.8(GND) U73.8(GND) ; also on sheet 4 6 7 8 9 10 11 12 13 14 15 16 17 24 25 26 27 28 29 30 32 33
VCC3V3_XDS: C271.2 C273.2 C274.1 R359.1 R360.1 R365.1 R366.1 R367.1 R368.1 R369.1 R370.1 R377.1 U56.1(VCC1) U57.1(VCC1) U58.1(VCC1) ; also on sheet 17 27 28
VCC_1V2: R75.2 TP28.1(TP) ; also on sheet 8
VCC_1V2_N: R70.2 R75.1
VCC_1V2_P: R68.2 R75.4
VDD_IO_3V3: R74.2 TP27.1(TP) ; also on sheet 8
VDD_IO_3V3_N: R71.2 R74.1
VDD_IO_3V3_P: R69.2 R74.4
VDDA_IO_3V3: C314.1 C315.1 C316.2 R406.1 R409.1 U68.5(VCC) U69.5(VCC) U70.8(VDD) U72.16(VCC) U73.16(VCC) ; also on sheet 6 16
ADC3_MUX_SEL: R405.1 U70.1(SEL1) U70.5(SEL2) ; also on sheet 12
ADC4_MUX_OE#: R407.1 U72.15(~{OE})
ADC4_MUX_SEL: R406.2 R408.1 U72.1(S) ; also on sheet 12
ADC5_MUX_OE#: R410.1 U73.15(~{OE})
ADC5_MUX_SEL: R409.2 R411.1 U73.1(S) ; also on sheet 12
ADC_CAL0: U73.2(1B1) ; also on sheet 16
ADC_CAL0/ADC_R0_AIN0: U73.4(1A) ; also on sheet 6
ADC_CAL1: U70.4(S2A) ; also on sheet 16
ADC_CAL1/ADC_R0_AIN1: U70.6(D2) ; also on sheet 6
ADC_R0_AIN0: U73.3(1B2) ; also on sheet 16
ADC_R0_AIN1: U70.7(S2B) ; also on sheet 16
ADC_R0_AIN2: U72.3(1B2) ; also on sheet 16
ADC_R0_AIN3: U72.6(2B2) ; also on sheet 16
ADC_R1_AIN0: U73.6(2B2) ; also on sheet 16
ADC_R1_AIN1: U70.9(S1B) ; also on sheet 16
ADC_R1_AIN2: U72.10(3B2) ; also on sheet 16
ADC_R1_AIN3: U72.13(4B2) ; also on sheet 16
BOOTMODE_TA_I2C_SCL: R361.2 ; also on sheet 11 28
BOOTMODE_TA_I2C_SDA: R362.2 ; also on sheet 11 28
BOOTMODE_XDS_I2C_SCL: R360.2 U56.3(SCL1) ; also on sheet 17
BOOTMODE_XDS_I2C_SDA: R359.2 U56.2(SDA1) ; also on sheet 17
HSEC_ADC2_AIN0: U73.5(2B1) ; also on sheet 16
HSEC_ADC2_AIN0/ADC_R1_AIN0: C322.1 U69.3(IO2) U73.7(2A) ; also on sheet 6
HSEC_ADC2_AIN1: U70.2(S1A) ; also on sheet 16
HSEC_ADC2_AIN1/ADC_R1_AIN1: C321.1 U69.1(IO1) U70.10(D1) ; also on sheet 6
HSEC_ADC3_AIN0: U72.2(1B1) ; also on sheet 16
HSEC_ADC3_AIN0/ADC_R0_AIN2: C324.1 U69.4(IO3) U72.4(1A) ; also on sheet 6
HSEC_ADC3_AIN1: U72.5(2B1) ; also on sheet 16
HSEC_ADC3_AIN1/ADC_R0_AIN3: C323.1 U69.6(IO4) U72.7(2A) ; also on sheet 6
HSEC_ADC3_AIN2: U72.11(3B1) ; also on sheet 16
HSEC_ADC3_AIN2/ADC_R1_AIN2: C320.1 U68.4(IO3) U72.9(3A) ; also on sheet 6
HSEC_ADC3_AIN3: U72.14(4B1) ; also on sheet 16
HSEC_ADC3_AIN3/ADC_R1_AIN3: C319.1 U68.6(IO4) U72.12(4A) ; also on sheet 6
HSEC_EPWM3_A: U73.11(3B1) ; also on sheet 27
HSEC_EPWM3_A/HSEC_MII1_CRS(RES0_PWMOUT0): C318.1 U68.3(IO2) U73.9(3A) ; also on sheet 6
HSEC_MII1_CRS(RES0_PWMOUT0): U73.10(3B2) ; also on sheet 6 32
SOC_I2C2_SCL: U12.5(SCL) U13.5(SCL) ; also on sheet 12 26 28
SOC_I2C2_SDA: U12.4(SDA) U13.4(SDA) ; also on sheet 12 26 28
TA_GPIO1: R371.2 ; also on sheet 10 28
TA_GPIO1_XDS: R365.2 U57.2(INA) ; also on sheet 17
TA_GPIO2: R378.2 ; also on sheet 28
TA_GPIO2_XDS: R377.2 U58.2(INA) ; also on sheet 17
TA_GPIO3: R372.2 ; also on sheet 11 28
TA_GPIO3_XDS: R366.2 U57.3(INB) ; also on sheet 17
TA_GPIO4: R373.2 ; also on sheet 11 28
TA_GPIO4_XDS: R367.2 U57.4(INC) ; also on sheet 17
TA_PORZn: R374.2 ; also on sheet 10 28
TA_PORZn_XDS: R368.2 U57.5(IND) ; also on sheet 17
TA_POWERDOWNz: R376.2 ; also on sheet 4 28
TA_POWERDOWNz_XDS: R370.2 U57.7(INF) ; also on sheet 17
TA_RESETz: R375.2 ; also on sheet 10 28
TA_RESETz_XDS: R369.2 U57.6(INE) ; also on sheet 17
VMAIN: R47.1 ; also on sheet 4 10 14 26 27 29
VSYS_1V2: R75.3 ; also on sheet 29
VSYS_1V2_PG: R76.2 ; also on sheet 10 29
VSYS_3V3_LDO1: R74.3 ; also on sheet 6 7 9 10 11 12 13 14 15 16 17 24 26 27 28 29 30 32 33
VSYS_3V3_LDO2: C89.1 C90.1 U12.6(VS) U13.2(A0) U13.6(VS) ; also on sheet 9 12 13 25 26 30
VSYS_TA_3V3: C272.2 C275.1 C351.2 R72.1 R73.1 U56.8(VCC2) U57.16(VCC2) U58.8(VCC2) ; also on sheet 11 28 29
XDS_GND: C271.1 C273.1 C274.2 U56.4(GND1) U57.8(GND1) U58.3(INB) U58.4(GND1) ; also on sheet 17 27 28
N34662299: R361.1 U56.6(SCL2)
N34662301: R362.1 U56.7(SDA2)
N34828765: LD5.2(ANODE) R72.2
N34828799: LD4.2(ANODE) R73.2
N34828801: LD4.1(CATHODE) Q2.3(D)
N34828819: Q2.1(G) R76.1
N34830317: C92.1 R69.1 U12.10(IN+)
N34830329: C92.2 R71.1 U12.8(VBUS) U12.9(IN-)
N34830425: C91.1 R68.1 U13.10(IN+)
N34830437: C91.2 R70.1 U13.8(VBUS) U13.9(IN-)
N35342843: R371.1 U57.15(OUTA)
N35343433: R372.1 U57.14(OUTB)
N35343436: R373.1 U57.13(OUTC)
N35343439: R374.1 U57.12(OUTD)
N35343442: R375.1 U57.11(OUTE)
N35343445: R376.1 U57.10(OUTF)
N35345342: R378.1 U58.7(OUTA)
N35656175: LD2.2(ANODE) R47.2

Not connected (* = marked no-connect by the designer): U12 3(ALERT)*; U13 3(ALERT)*; U68 1(IO1)*; U73 12(4A)* 13(4B2)* 14(4B1)*

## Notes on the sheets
sheet 1
- Current Monitors
- I2C ADDRESS:(0x40)
- I2C ADDRESS:(0x41)
- Voltage In-Line Resistors
- Power LEDs
- GREEN
- GREEN
- GREEN
sheet 2
- ADC MUXES
- CAD NOTE: Place the ESDs close to connector
- CAD NOTE: Place the CAPs close to each other
- CAD NOTE: Place the CAPs close to  connector
sheet 3
- BOOTMODE_I2C_TA BUFFER
- ISOLATION BUFFERS FOR TA SIGNALS
